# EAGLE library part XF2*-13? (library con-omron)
OMRON FPC Connector Source : http://www.omron.com/ecb/products/pdf/fpc.pdf
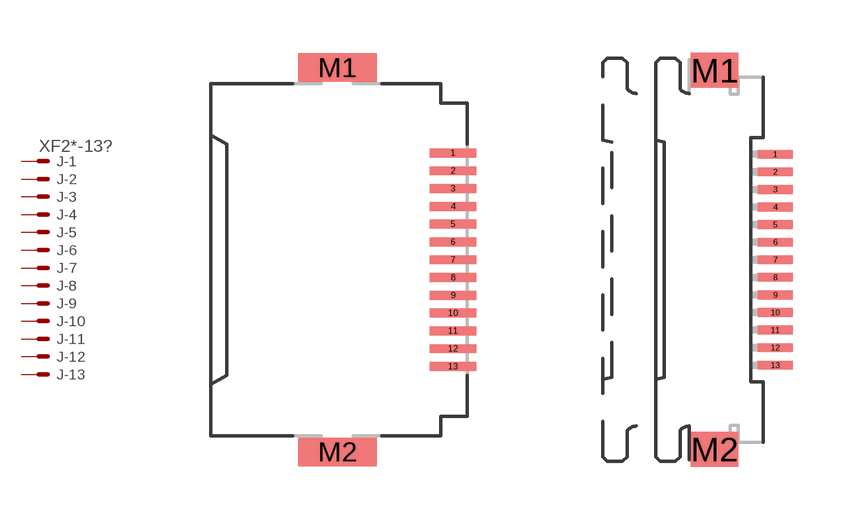
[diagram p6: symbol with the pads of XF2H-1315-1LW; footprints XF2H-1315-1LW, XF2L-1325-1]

Designator prefix J; gates -1=PV -2=P -3=P -4=P -5=P -6=P -7=P -8=P -9=P -10=P -11=P -12=P -13=P

## XF2H-1315-1LW (OC_FARNELL: unknown; OC_NEWARK: unknown)  [XF2H-1315-1LW]
1  -1:MSV  pas
2  -2:MS  pas
3  -3:MS  pas
4  -4:MS  pas
5  -5:MS  pas
6  -6:MS  pas
7  -7:MS  pas
8  -8:MS  pas
9  -9:MS  pas
10  -10:MS  pas
11  -11:MS  pas
12  -12:MS  pas
13  -13:MS  pas

## XF2L-1325-1 (MF: OMRON COMPONENTS USA; MPN: XF2L-1325-1; OC_FARNELL: unknown; OC_NEWARK: 89C8588)  [XF2L-1325-1]
Pads as for XF2H-1315-1LW

## XF2L-1335-1 (MPN: XF2L-1335-1; OC_FARNELL: unknown; OC_NEWARK: 37M0884)  [XF2L-1335-1]
Pads as for XF2H-1315-1LW

## Footprint XF2H-1315-1LW (pad centres in mm)
Standard Rotary Backlock Type (0.5 mm-pitch) Source : http://www.omron.com/ecb/products/pdf/fpc.pdf
smd 1.3 x 0.25: 1 3.175,3; 2 3.175,2.5; 3 3.175,2; 4 3.175,1.5; 5 3.175,1; 6 3.175,0.5; 7 3.175,0; 8 3.175,-0.5; 9 3.175,-1; 10 3.175,-1.5; 11 3.175,-2; 12 3.175,-2.5; 13 3.175,-3
smd 2.2 x 0.8: M1 -0.075,5.4; M2 -0.075,-5.4

## Footprint XF2L-1325-1 (pad centres in mm)
ZIF Slide-locking Type (0.5 mm-pitch) Upper-contact Type Source : http://www.omron.com/ecb/products/pdf/fpc.pdf
smd 1 x 0.25: 1 1.905,3; 2 1.905,2.5; 3 1.905,2; 4 1.905,1.5; 5 1.905,1; 6 1.905,0.5; 7 1.905,0; 8 1.905,-0.5; 9 1.905,-1; 10 1.905,-1.5; 11 1.905,-2; 12 1.905,-2.5; 13 1.905,-3
smd 1.34 x 1: M1 0.18,5.388; M2 0.18,-5.388

## Footprint XF2L-1335-1 (pad centres in mm)
ZIF Slide-locking Type (0.5 mm-pitch) Lower-contact Type Source : http://www.omron.com/ecb/products/pdf/fpc.pdf
smd 1 x 0.25: 1 1.905,3; 2 1.905,2.5; 3 1.905,2; 4 1.905,1.5; 5 1.905,1; 6 1.905,0.5; 7 1.905,0; 8 1.905,-0.5; 9 1.905,-1; 10 1.905,-1.5; 11 1.905,-2; 12 1.905,-2.5; 13 1.905,-3
smd 1.34 x 1: M1 0.18,5.388; M2 0.18,-5.388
